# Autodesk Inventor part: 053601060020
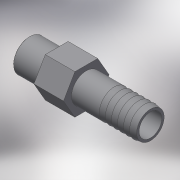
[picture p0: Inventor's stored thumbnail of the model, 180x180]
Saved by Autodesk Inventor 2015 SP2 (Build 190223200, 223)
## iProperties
Created: 2017-10
Part Number: 053601060020
Material: Generic
Description: PLASSON THREADED HOSE NOZZLE 2"-60
Document SubType Name: Modeling
Designer: KIM
Density: 1 g/cm^3
Appearance: Default
Author: KIM
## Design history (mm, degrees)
derived "053601.ipt"
feature "Solid1::053601.ipt"
tag "TaggingFeature1"
body "Solid1"
other parameters: "d0" = 118, "d1" = 170 deg, "d6" = 41.7298, "d8" = 35.4, "d9" = 59.614, "d10" = 65, "d11" = 26, "d12" = 16, "d13" = 16, "d14" = 0, "d15" = 0.12, "d_" = 12, "H_" = 118, "R_" = 59.614, "C_" = 65, "B_" = 16, "Lt_" = 26
